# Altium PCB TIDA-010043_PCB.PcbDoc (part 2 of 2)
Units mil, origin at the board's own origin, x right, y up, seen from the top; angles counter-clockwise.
Board outline 2300 x 1555.91 mil, 4 copper layers (Top Layer, GND, PWR, Bottom Layer), stack 84.834 mil thick; 121 components, 65 nets, 295 pads, 120 vias.
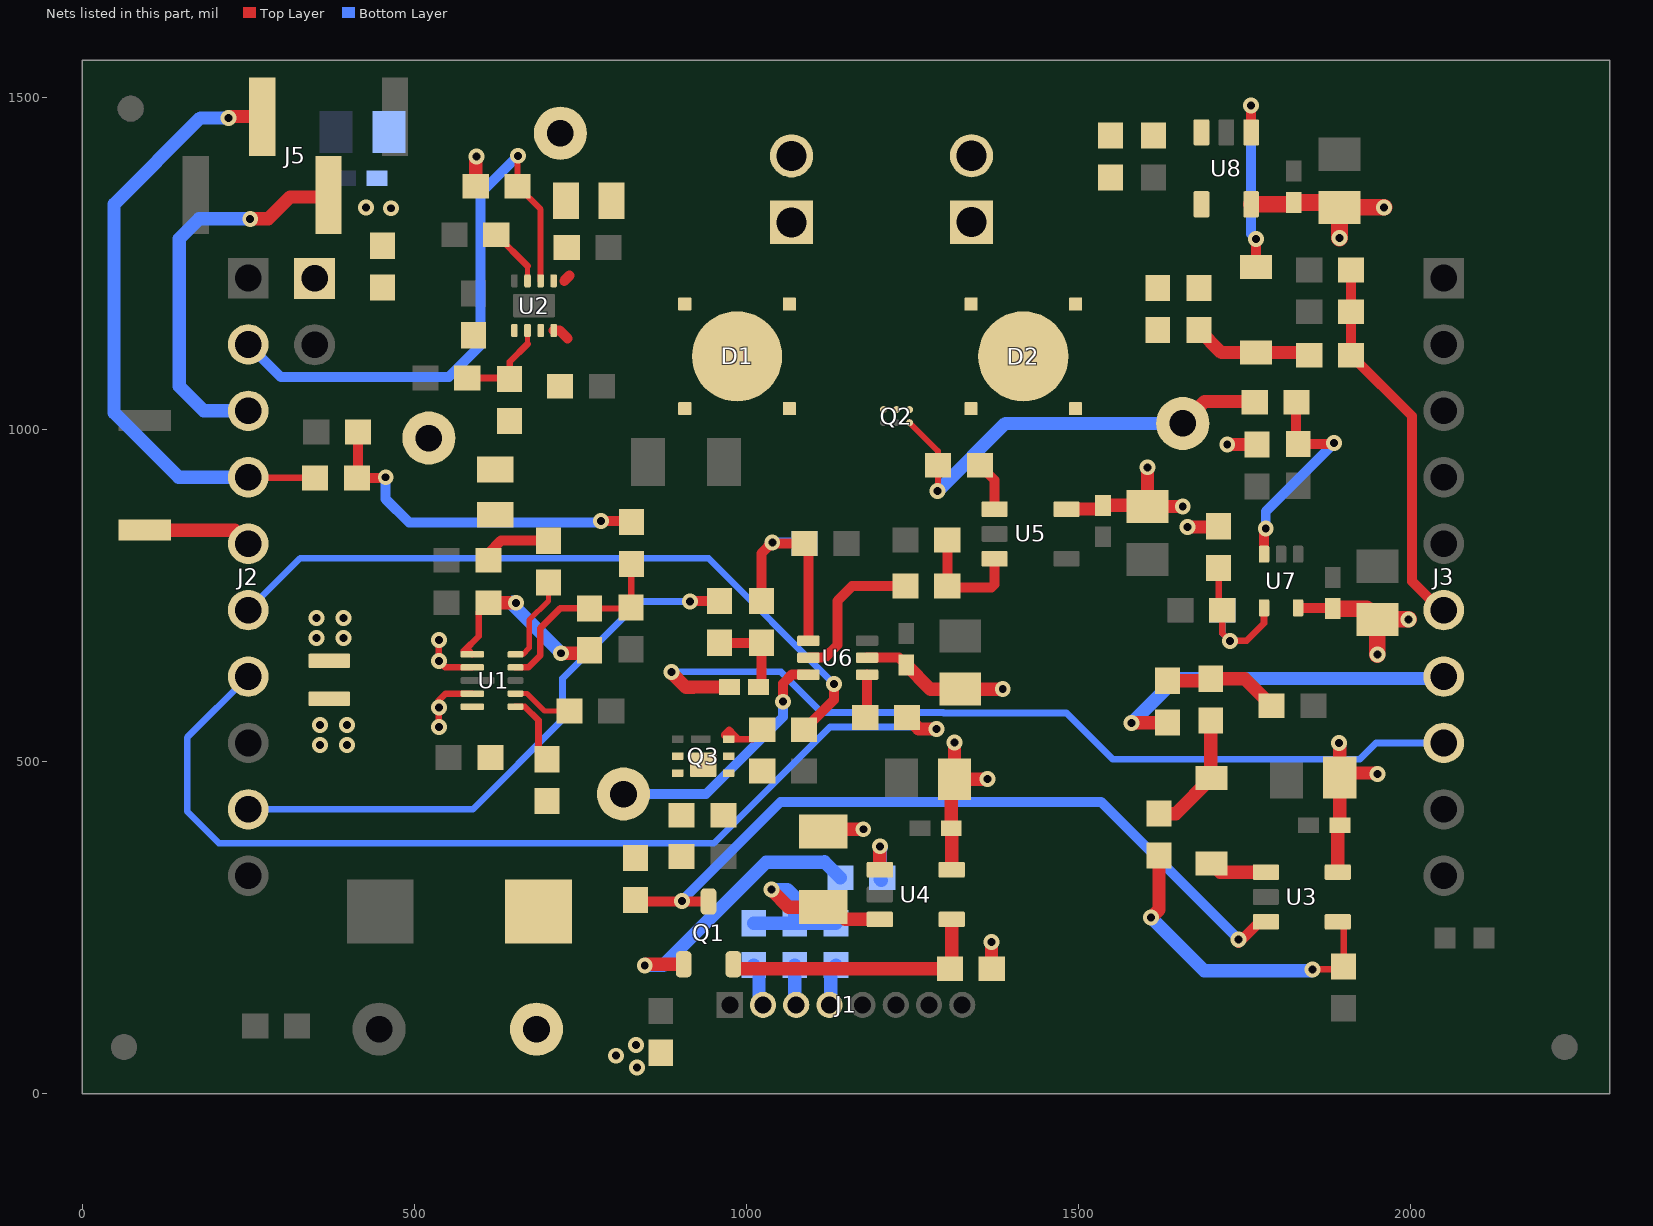
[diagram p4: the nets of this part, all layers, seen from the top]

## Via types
v1: diameter 24, hole 12, Top Layer to Bottom Layer, tented both sides, 114 vias
v2: diameter 24, hole 12, Top Layer to Bottom Layer, 4 vias
v3: diameter 19.68, hole 7.87, Top Layer to Bottom Layer, 2 vias

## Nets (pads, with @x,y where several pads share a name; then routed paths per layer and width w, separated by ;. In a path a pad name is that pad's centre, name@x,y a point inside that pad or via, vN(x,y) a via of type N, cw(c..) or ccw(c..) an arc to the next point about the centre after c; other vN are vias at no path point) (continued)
MUX_CTRL: J2.7 R30.1 | length 1513.6
  Top Layer w20: R30.1@1242.05,566.21 1259.26,549 v1(1286,549)
  Bottom Layer w10: J2.7@250,627.95 158,535.95 158,425 206,377 951,377 1125.87,551.87 1283.13,551.87 v1(1286,549)
NetC1_1: C1.1 C25.1 R5.1 U1.10 VIN.1
NetC2_1: C2.1 C3.1 R1.1 R4.2 R6.1 U1.6 | length 412
  Top Layer w9.84: U1.6@587.39,661.32 582.24,666.48 574.8,666.48 597,688.67 597,724.38 C3.1@611.62,739
  Top Layer w15: C2.1@611.62,803 611.62,813.82 630.24,832.44 R6.1@702,832.44
  Top Layer w20: C3.1@611.62,739 v1(653,739) ; v1(721,663) 759.5,663 R4.2@764,667.5
  Bottom Layer w20: v1(653,739) 649,739 648,740 646,738 v1(721,663)
NetC4_1: C4.1 R2.1 TP3.1 U2.5 | length 11.6
  Top Layer w15: 725.77,1223.77 734,1232
NetC5_1: C5.1 R1.2 R7.2 TP2.1 U2.3 U2.4 | length 26.1
  Top Layer w15: U2.4@709.85,1148.96 719.04,1148.96 731,1137
NetC6_1: C6.1 U2.1
NetC7_1: C7.1 R12.1 R13.1 | length 536.1
  Top Layer w15: C7.1@415.5,996 415.5,929 R13.1@413.5,927 456,927 v1(457,928) ; v1(781,862) 826.5,862 R12.1@828,860.5 ; R12.1@830,868.5 R12.1@831.5,869.99
  Bottom Layer w15: v1(457,928) 457,895 492.37,859.63 778.63,859.63 v1(781,862)
NetC17_1: C17.1 R23.2 U5.3 | length 182
  Top Layer w15: C17.1@1302.5,833.53 R23.2@1302.5,764 1304.5,762 1369,762 1373.71,766.71 U5.3@1373.71,805.22
NetC22_1: C22.1 Q3.3 R29.2 | length 102.7
  Top Layer w10: Q3.3@973.39,533.59 972.9,533.59 966.48,540.01 ; Q3.3@980.8,533.59 988.1,533.59 ; 980.8,541 974.43,547.36 973.83,547.36 966.48,540.01 ; R29.2@1023.85,547.7 1009.74,533.59 988.1,533.59 ; 966.48,540.01 981.68,540.01 988.1,533.59
NetC23_1: C23.1 R31.1 R33.2 U7.4 | length 252.9
  Top Layer w10: R31.1@1711,791.22 1711,733.21 C23.1@1716.5,727.71 1716.5,693.22 v1(1728,681.71) 1753,681.71 1779.41,708.12 U7.4@1779.41,731.36
  Bottom Layer w10: R33.2@1716.5,727.71 1716.5,693.22 v1(1728,681.71)
NetC24_1: C24.1 R34.1 R36.2 U6.4 | length 342.3
  Top Layer w15: R34.1@1022.56,741.7 1022.56,813.56 v1(1039,830) 1040.79,828.21 R36.2@1087.5,828.21 1093.26,822.45 U6.4@1093.26,681.85
  Bottom Layer w15: v1(1039,830) 1085.71,830 C24.1@1087.5,828.21
NetC26_1: C26.1 R39.2 R40.1 | length 174.5
  Top Layer w20: R40.1@1634.29,621.5 1696.29,621.5 R39.2@1699.29,624.5 1750.3,624.5 C26.1@1790.79,584
NetD1_1: D1.1 D1.4 D1.5 J8.1
NetD1_2: D1.2 D1.3 D2.1 D2.4 Q2.A1 Q2.B1 Q2.C1 R16.1
NetD2_2: D2.2 D2.3 D2.5 J6.1
NetD3_2: D3.2 R34.2 R35.1 | length 131.3
  Top Layer w15: R35.1@959.56,678.71 R34.2@1022.56,678.71 1022.56,616.56 D3.2@1018.21,612.21
NetD4_1: D4.1 R38.2 R39.1 | length 189
  Top Layer w20: R38.2@1621.29,421.5 1646.31,421.5 D4.1@1700.29,475.47 1699.29,476.47 R39.1@1699.29,561.5 R39.1@1700.1,562.32
NetD4_2: D4.2 U3.1 | length 87.3
  Top Layer w20: D4.2@1700.29,346.53 1713.42,333.4 U3.1@1782.15,333.4
NetD5_1: D5.1 R14.2 R17.1 | length 181.9
  Top Layer w20: R14.2@1681.32,1149.72 1715.29,1115.75 D5.1@1767.32,1115.75 1843.44,1115.75 R17.1@1847.5,1111.68
NetD5_2: D5.2 U8.1 | length 287.1
  Top Layer w15: U8.1@1760,1447.22 v1(1760,1488) ; D5.2@1767.32,1244.68 v1(1767.32,1286.68)
  Bottom Layer w15: v1(1760,1488) 1760,1294 v1(1767.32,1286.68)
NetJ6_2: J6.2 J8.2 R2.2 R18.1
NetL1_1: L1.1 U1.9 | length 94.6
  Top Layer w9.84: v2(537,552) v2(537,581) 537,592 547.27,602.27 U1.9@587.39,602.27
  other v1: 358,525 398.65,525 358,555 398.65,555
NetL1_2: L1.2 U1.7 | length 86
  Top Layer w9.84: v2(537,683) v2(537,651.46) 546.82,641.64 U1.7@587.39,641.64
  other v1: 353,686 393.65,686 353,716 393.65,716
NetQ1_1: Q1.1 R21.2 | length 429.9
  Top Layer w20: v1(847,193) v1@848,194 ; v1@849,194 v1@848,194 ; Q1.1@905.6,194.76 848.76,194.76 v1@848,194
  Bottom Layer w20: v1(847,193) 875,193 1030.13,348.13 1117.56,348.13 1117.56,349 R21.2@1141.5,325.05
NetQ1_2: Q1.2 R15.1 U4.4 | length 404.3
  Top Layer w20: Q1.2@980.4,194.76 987.16,188 R15.1@1306.5,188 1309.13,190.63 U4.4@1309.13,262.28
NetQ1_3: Q1.3 R42.2 U3.3 | length 1156.1
  Top Layer w15: R42.2@833,291.5 835.26,289.24 Q1.3@943,289.24 ; v1(1741.29,232) 1741.29,227 1772.89,258.6 U3.3@1782.15,258.6
  Bottom Layer w15: v1(903,290) 903,290.71 1051.29,439 1534.29,439 v1(1741.29,232)
NetQ2_A2: Q2.A2 R22.2 R43.1 TP6.1 | length 655.9
  Top Layer w9: Q2.A2@1245.68,1010.16 1288.5,967.34 R22.2@1288.5,946 1288.5,907.5 v1(1288,907)
  Top Layer w20: TP6.1@1657,1009 1690.08,1042.08 1758.88,1042.08 R43.1@1764.5,1047.71
  Bottom Layer w20: v1(1288,907) 1390,1009 TP6.1@1657,1009
NetQ3_1: Q3.1 Q3.2 Q3.5 Q3.6 Q3.8 R25.1
NetR4_1: R4.1 R10.1 R12.2 U1.4 | length 301.3
  Top Layer w9.38: R4.1@764,730.5 825.05,730.5 R10.1@826.5,731.94 826.5,797 R12.2@827,797.5
  Top Layer w9.84: U1.4@652.35,641.64 671.61,641.64 689.98,660 689.98,700.98 719.5,730.5 R4.1@764,730.5
NetR5_2: R5.2 U1.1 | length 107.1
  Top Layer w9.84: U1.1@652.35,582.58 666.42,582.58 687,562 687,516.5 R5.2@700,503.5
NetR6_2: R6.2 U1.5 | length 135.2
  Top Layer w8: U1.5@652.35,661.32 663.39,661.32 672.9,670.83 672.9,712.82 702,741.93 R6.2@702,769.45
NetR7_1: R7.1 R11.2 U2.2 | length 146.6
  Top Layer w8: 670.48,1128.52 U2.2@670.48,1148.96
  Top Layer w10: R11.2@579.82,1077.37 643.82,1077.37 643.82,1101.87 670.48,1128.52
NetR8_2: R8.2 U1.2 | length 92
  Top Layer w8: U1.2@652.35,602.27 669.73,602.27 696,576 R8.2@733.5,576
NetR9_2: R9.2 U2.7 | length 88.7
  Top Layer w8: U2.7@670.48,1223.77 670.48,1246.02
  Top Layer w10: R9.2@623.5,1293 670.48,1246.02
NetR14_1: R14.1 R16.2 U8.4
NetR18_2: R18.2 R20.2 U8.3
NetR19_1: R19.1 R46.2 R47.2 R48.2 U4.3 | length 384.9
  Top Layer w20: v1(1038,307) 1038,306 1063.4,280.6 R19.1@1116,280.6 1130.2,280.6 1148.51,262.28 U4.3@1200.87,262.28
  Bottom Layer w20: R46.2@1011,256.5 R47.2@1072.94,256.5 ; v1(1038,307) 1062,307 1072.94,296.06 R47.2@1072.94,256.5 ; R48.2@1134.87,256.5 R47.2@1072.94,256.5
NetR21_1: R21.1 U4.1 | length 90.3
  Top Layer w20: U4.1@1200.87,337.09 1200.87,371.8 v1(1201.43,372.37)
  Bottom Layer w20: R21.1@1203,320.99 1201.43,322.56 v1(1201.43,372.37) v1@1203.38,370.41
NetR22_1: R22.1 U5.1 | length 75.2
  Top Layer w15: R22.1@1351.5,946 1373.71,923.79 U5.1@1373.71,880.02
NetR23_1: R23.1 U6.5 | length 229.9
  Top Layer w15: U6.5@1093.26,656.26 1117.87,656.26 1137,675.39 1137,742 1159,764 R23.1@1239.5,764
NetR25_2: R25.2 R26.2 R42.1 TP5.1 U6.6 | length 382.2
  Top Layer w15: v1(1055,590) 1055,617.33 1068.33,630.67 U6.6@1093.26,630.67
  Bottom Layer w15: TP5.1@815,451 939,451 1055,567 v1(1055,590)
NetR30_2: R30.2 U6.1 | length 65.6
  Top Layer w15: R30.2@1179.06,566.21 1181.85,569 U6.1@1181.85,630.67
NetR37_2: R37.2 R38.1 U3.4 | length 482.5
  Top Layer w10: v1(1852.29,187) 1894.79,187 R37.2@1899.29,191.5 U3.4@1899.29,249.73
  Top Layer w20: v1(1609.29,265) 1621.29,277 R38.1@1621.29,358.5
  Bottom Layer w20: v1(1609.29,265) 1689.29,185 1850.29,185 v1(1852.29,187)
NetR43_2: R43.2 R44.1 U7.3 | length 336.7
  Top Layer w15: U7.3@1779.41,812.07 1779.41,848.12 v1(1782,850.71) ; R43.2@1827.5,1047.71 1827.5,981.71 R44.1@1831,978.21 1883.65,978.21 v1(1885,979.56)
  Bottom Layer w15: v1(1782,850.71) 1782,876.56 v1(1885,979.56)
PEAK-DETECT: J3.7 R40.2 | length 553.5
  Top Layer w20: v1(1580,558) 1580.5,558.5 R40.2@1634.29,558.5
  Bottom Layer w20: v1(1580,558) 1647,625 2047.05,625 J3.7@2050,627.95
PWM_CAL: J2.9 R35.2 | length 875.8
  Top Layer w15: v1(915,741) 915.7,741.7 R35.2@959.56,741.7
  Bottom Layer w10: J2.9@250,427.95 587.95,427.95 723.13,563.13 723.13,625.13 839,741 v1(915,741)
PWM_DCDC: J2.4 J5.2 R13.2 | length 934.8
  Top Layer w10: J2.4@250,927.95 250.95,927 R13.2@350.5,927
  Top Layer w20: v1(220,1469) 222.06,1471.06 J5.2@271,1471.06
  Bottom Layer w20: v1(220,1469) 178,1469 48,1339 48,1025 145.05,927.95 J2.4@250,927.95
RANGE_SEL: J2.6 R29.1 | length 1080.6
  Top Layer w15: R29.1@1086.84,547.7 1132,592.86 v1(1132,616.91)
  Bottom Layer w10: J2.6@250,727.95 328.05,806 942.91,806 v1(1132,616.91)
RXD: J2.3 J5.3 | length 593.7
  Top Layer w20: v1(253,1317) 280,1317 313,1350 J5.3@368.06,1350 ; J5.3@368.06,1367 J5.3@371,1369.94
  Bottom Layer w20: J2.3@250,1027.95 183.05,1027.95 146,1065 146,1287 176,1317 v1(253,1317)
SW_CAL: D3.1 J3.8 | length 1326
  Top Layer w20: v1(887,635) 887,634 909,612 920,612 920.21,612.21 D3.1@974.9,612.21
  Bottom Layer w10: v1(887,635) 1052.11,635 1113.23,573.87 1296.3,573.87 1297.18,573 1482,573 1551.87,503.13 1923.13,503.13 1947.95,527.95 J3.8@2050,527.95
SW_X: J2.5 S2.1 | length 164.4
  Top Layer w20: S2.1@94,848.32 229.63,848.32 J2.5@250,827.95
TX_3: J1.2 R46.1 | length 65.7
  Bottom Layer w20: R46.1@1011,193.5 1019,185.5 1019,139.61 J1.2@1025,133.61
TX_N: J1.4 R48.1 | length 64
  Bottom Layer w20: J1.4@1125,133.61 1127,135.61 1127,185.63 R48.1@1134.87,193.5
TX_P: J1.3 R47.1 | length 60.7
  Bottom Layer w20: R47.1@1072.94,193.5 1072.94,135.68 J1.3@1075,133.61
V_FAULT: J2.2 R3.1 U2.6 | length 901.2
  Top Layer w9: v1(656,1412) 655.5,1411.5 R3.1@655.5,1366 690.16,1331.33 U2.6@690.16,1223.77
  Bottom Layer w15: J2.2@250,1127.95 298.95,1079 552,1079 600,1127 600,1356 v1(656,1412)
V_LED: C12.1 J3.6 R17.2 R41.2 | length 574.7
  Top Layer w15: R41.2@1910.5,1240.22 C12.1@1910.5,1177.22 R17.2@1910.5,1111.68 2002,1020.18 2002,771.3 2047.67,725.63 J3.6@2050,727.95
VCC_5V: C8.1 C9.1 C10.1 C11.1 C13.1 C14.1 C15.1 C16.1 C18.1 C19.1 C20.1 C21.1 C27.1 C28.1 R3.2 R15.2 R19.2 R24.2 R27.2 R31.2 R32.2 U3.5 U4.5 U5.5 U6.2 U7.5 U8.5 | length 1683.3
  Top Layer w15: U6.2@1181.85,656.26 1229.89,656.26 C16.1@1240.56,645.59 ; U7.5@1830.59,731.36 1881.73,731.36 C21.1@1883,730.09
  Top Layer w20: R3.2@592.5,1366 592.5,1409.5 v1(594,1411) ; R19.2@1116,394.77 1119.23,398 v1(1176,398) ; C16.1@1240.56,645.59 1277.14,609 C15.1@1322,609 v1(1386,609) ; U4.5@1309.13,337.09 1309.13,398.66 C11.1@1308.43,399.37 1308.43,468.37 C10.1@1313.43,473.37 ; v1(1313.43,528.43) C10.1@1313.43,473.37 ; v1(1363.37,473.37) C10.1@1313.43,473.37 ; v1(1369,228) 1369,188.5 R15.2@1369.5,188 ; U5.5@1481.98,880.02 1531.4,880.02 C14.1@1537,885.62 1602.38,885.62 C13.1@1604,884 ; v1(1604,943) C13.1@1604,884 ; v1(1657,884) C13.1@1604,884 ; v1(1664,853) 1696.78,853 1704.5,860.71 R31.2@1711,854.21 ; v1(1724,977.21) R32.2@1769,977.21 ; U3.5@1890.42,333.4 1890.42,400.89 C28.1@1893.53,404 1893.53,475.76 C27.1@1893.29,476 ; v1(1892.29,528) 1893.29,527 C27.1@1893.29,476 ; v1(1950,481) 1948.31,482.69 1899.98,482.69 C27.1@1893.29,476
  Top Layer w25: U8.5@1760,1338.95 1821.35,1338.95 C9.1@1824,1341.59 1885.62,1341.59 C8.1@1893,1334.22 ; C21.1@1883,730.09 1933.91,730.09 C20.1@1950,714 ; v1(1893,1288) C8.1@1893,1334.22 ; v1(1950,661) C20.1@1950,714 ; v1(1960.22,1334.22) C8.1@1893,1334.22 ; v1(1997.11,714) C20.1@1950,714
  other v1: 835,39 804,57 834,73 465,1333 427,1334
VCC_5V_LP: J4.1 R24.1
pads on no net: FID1.1 FID2.1 FID3.1 FID4.1 FID5.1 FID6.1 J1.6 J1.7 J1.8 J2.8 J2.10 J3.3 J3.4 J3.5 Q3.0 U2.9@662.6,1186.37 U2.9@698.04,1186.37

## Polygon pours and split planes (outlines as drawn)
NetJ6_2 on Top Layer "vdd" (solid, remove dead copper, pour order 104): 969,1379 904,1314 779,1314 776,1317 776,1375 782,1381 869,1381 951,1463 1420,1463 1486,1397 1568,1397 1574,1391 1574,1356 1568,1350 1440.95,1350 1411.95,1379
VCC_5V on Top Layer "Top Layer-No Net" (solid, pour order 78): 431,1258.3 434.3,1255 470,1255 474,1259 474,1311 514,1351 514,1392 507,1399 414,1399 405,1390 405,1313.46 431,1287.46
GND on Top Layer "Top Layer-No Net" (solid, pour order 76): 158,162 168,172 271,172 284,159 284,66 276,58 174,58 158,74
VCC_5V_LP on Top Layer "Top Layer-No Net" (solid, pour order 72): 385,1259 402,1259 426,1235 469,1235 470.7,1233.3 470.7,1193.7 461,1184 314,1184 301,1197 301,1252 308,1259
NetR18_2 on Top Layer "TOP_LAYER_NETR18_2_P052" (solid, remove dead copper, pour order 52): 1687.51,1418.51 1529.21,1418.51 1523.46,1424.26 1523.46,1480.46 1530.46,1487.46 1701.02,1487.46 1703,1485.48 1703,1434
NetL1_2 on Top Layer "TOP_LAYER_NETL1_2_P004" (solid, remove dead copper, pour order 4): 422,638 424,640 424,738 419,743.38 337.38,743.38 332,738 332,641 335,638
NetL1_1 on Top Layer "TOP_LAYER_NETL1_1_P012" (solid, remove dead copper, pour order 12): 414.62,502.62 423,511 422,512 422,601 418,605 414,605.3 338.3,605.3 330,597 330,518 345.38,502.62
NetC1_1 on Top Layer "TOP_LAYER_NETC1_1_P016" (solid, remove dead copper, pour order 16): 666,520 666,468.54 673.54,461 725.17,461 741.08,444.92 764,422 764,40 753,29 614,29 593,50 593,541.54 569,565.54 569,586.21 570.59,587.8 593,587.8 606.54,587.8 666,528.34
GNDP on Top Layer "TOP_LAYER_GNDP_P018" (solid, remove dead copper, pour order 18): 621.84,617.33 571.6,617.33 567,612.73 567,531 572,526 572,45 553,26 305,26 304,27 304,864 322,882 549,882 567,864 567,657 567,630 570,627 621.84,627
GND on Top Layer "TOP_LAYER_GND_P022" (solid, remove dead copper, pour order 22): 846,612 846,688.33 807,688.37 807,647 800,640 685.26,640 672.26,627 641.38,627 640.38,626 640.38,617.8 641,617.1 672.9,617.1 685.46,604.54 749,604.54 838.54,604.54
NetC6_1 on Top Layer "TOP_LAYER_NETC6_1_P026" (solid, remove dead copper, pour order 26): 654.69,1159 656.32,1157.37 656.32,1132.37 644.32,1120.37 568.32,1120.37 568.32,1159
GND on Top Layer "TOP_LAYER_GND_P028" (solid, remove dead copper, pour order 28): 646.63,1244.37 656,1235 656,1194.12 658.38,1191.73 658.38,1185.38 653,1180 642.38,1180 637,1185.38 558.38,1185.38 548.32,1175.32 548.32,1055.37 495,1055.37 495,1295 520.27,1320.27 583.73,1320.27 586.85,1316.85 592,1311.7 592,1259 606.63,1244.37
NetC5_1 on Top Layer "TOP_LAYER_NETC5_1_P030" (solid, remove dead copper, pour order 30): 486.37,1035.37 478,1027 478,933 491,920 725,920 738.32,933.32 738.32,1148.96 730.28,1157 695.32,1157 685,1146.68 685,1061.05 659.32,1035.37
NetC4_1 on Top Layer "TOP_LAYER_NETC4_1_P032" (solid, remove dead copper, pour order 32): 703.89,1215 704.89,1214 750,1214 751,1215 751,1353.99 751,1394 773,1416 773,1484 763,1494 683,1494 670.76,1481.76 670.76,1420.24 703.89,1387.11 703.89,1346
NetD1_1 on Top Layer "TOP_LAYER_NETD1_1_P036" (solid, remove dead copper, pour order 36): 1118,1153 1104,1139 893,1139 873,1159 873,1222 898,1247 1004,1247 1013,1257 1013,1338.95 1021.05,1347 1104,1347 1118,1333
NetD2_2 on Top Layer "TOP_LAYER_NETD2_2_P038" (solid, remove dead copper, pour order 38): 1401,1247 1390,1258 1390,1338 1382,1346 1295,1346 1289,1340 1289,1154.5 1302.5,1141 1525,1141 1543,1159 1543,1236 1532,1247
NetD1_2 on Top Layer "TOP_LAYER_NETD1_2_P040" (solid, remove dead copper, pour order 40): 1644,1080 1578,1014 1578,958 1555,935 1425,935 1364,996 1332,996 1320,996 1292.36,1023.64 1117.64,1023.64 1095,1001 870,1001 861,1010 861,1068 868,1075 1546,1075 1568,1097 1568,1168 1573,1173 1640,1173 1644,1169
I_SENSE on Top Layer "TOP_LAYER_I_SENSE_P042" (solid, remove dead copper, pour order 42): 1233,1017 1233,916 1205,888 943,888 928,903 928,988 932,992 1102,992 1127,1017
NetQ2_A2 on Top Layer "TOP_LAYER_NETQ2_A2_P044" (solid, remove dead copper, pour order 44): 1238,1017 1238,920 1265,893 1308,893 1315,900 1315,993 1289,1019 1241,1019
NetR14_1 on Top Layer "TOP_LAYER_NETR14_1_P054" (solid, remove dead copper, pour order 54): 1673.48,1359.95 1668.48,1354.78 1668.48,1294.95 1651.48,1277.95 1597.48,1277.95 1588.26,1268.72 1588.26,1190.18 1595.48,1182.95 1695.48,1182.95 1707,1194.46 1707,1350 1697.05,1359.95
LED_DRV_SUP on Top Layer "TOP_LAYER_LED_DRV_SUP_P058" (solid, remove dead copper, pour order 58): 828,152.58 829.58,152.58 834.33,157 991.61,157 996,152.61 996,114 992,110 992,109 987,104 847.46,104 828,123.46
NetQ3_1 on Top Layer "TOP_LAYER_NETQ3_1_P060" (solid, remove dead copper, pour order 60): 884,515 884,472.39 889.72,466.66 929.34,466.66 936,460 936,403 944,395 986,395 986,517 983,520 888,520
NetC22_1 on Top Layer "TOP_LAYER_NETC22_1_P062" (solid, remove dead copper, pour order 62): 961.21,564.36 968.85,572 1042,572 1048,566 1048,467 1045,464 1004,464 1000,468 1000,513 988,525 969,525 961.21,532.79
NetR25_2 on Top Layer "TOP_LAYER_NETR25_2_P064" (solid, remove dead copper, pour order 64): 799,329 924.7,329 934,338.3 934,436.54 865.54,505 787,505 766,484 766,400 784,382 784,344
VCC_5V on Top Layer "Top Layer-No Net" (solid, pour order 102): 800,88 889,88 896,81 896,40 879,23 795,23 785,33 785,75 798,88
NetC2_1 on Top Layer "Bottom Layer-+5V" (solid, remove dead copper, pour order 106): 653,841.69 655,839.69 655,825 653,823 653,778 632,757 632,667.21 620.79,656 570,656 570,668.91 591,689.91 591,890 594,893 650,893 653,890
VCC_5V on Bottom Layer "Top Layer-No Net" (solid, pour order 82): 411,1321 411,1346 424,1359 424,1477 434,1487 500,1487 503,1484 503,1329 492,1318 414,1318
NetL1_2 on Bottom Layer "Top Layer-No Net" (solid, pour order 92): 589,729 590,728 590,640 586,636 545.22,636 334,636 331,639 331,723 337,729
NetL1_1 on Bottom Layer "Top Layer-No Net" (solid, pour order 94): 594,512 595,513 595,601 591,605 550.22,605 339,605 336,602 336,518 342,512
I_SENSE on Bottom Layer "BOTTOM_LAYER_I_SENSE_P100" (solid, remove dead copper, pour order 100): 1234,1018 1234,917 1206,889 944,889 929,904 929,989 933,993 1103,993 1128,1018
I_SENSE on PWR "PWR_I_SENSE_P096" (solid, remove dead copper, pour order 96): 1234,1018 1234,917 1206,889 944,889 929,904 929,989 933,993 1103,993 1128,1018
VCC_5V on PWR "Top Layer-No Net" (solid, pour order 98): 378,1470.14 440.86,1533 485,1534 2127,1534 2273,1388 2273,238 2168,133 1135,133 1135,1014 1121,1028 939.33,1028 867,954.22 867,33 852,18 615,18 424.73,208.27 424.73,1248.27 378,1295
GND on GND "Top Layer-No Net" (solid, pour order 90): 18,1432 18,1516 37,1535 2267,1535 2293,1509 2293,23 2286,16 34,16 18,32
GNDP on GND "Top Layer-No Net" (solid, pour order 88): 692,1093 744,1145 744,1298 759,1313 904,1313 924,1293 924,982 924,891 739,706 739,576.25 792,523.25 792,57 766,31 315,31 292,54 292,915 470,1093

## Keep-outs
Keep-Out Layer:
  the board outline again, w10
  text ".Layer_Name" at 577,-1080.54 h60

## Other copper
Top Layer:
  text ".Layer_Name" at 577,-1080.54 h60
GND:
  text "'.Layer_Name'" at 829,-1082 h60
PWR:
  text "'.Layer_Name'" at 785,-1086 h60
Bottom Layer:
  text ".Layer_Name" at 577,-1080.54 h60

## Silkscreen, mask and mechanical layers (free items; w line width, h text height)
Top Overlay:
  lines w6: 328,577 328,674 339,674 ; 531,620 557,620 ; 922,574 930,566 981,566 ; 1613,1080.25 1622.25,1071 1687.62,1071 1720,1038.62 1720,1016.19 1730.49,1005.7 1741.73,1005.7 ; 1957,1113 1966,1122 1966,1274 2001,1309 2019,1309
  text "TIDA-010043-E2" at 930,1487 h40
  text ".Layer_Name" at 577,-1080.54 h60
Bottom Overlay:
  text ".Layer_Name" at 577,-1080.54 h60
Top Paste:
  text ".Layer_Name" at 577,-1080.54 h60
Bottom Paste:
  text ".Layer_Name" at 577,-1080.54 h60
Top Solder:
  text ".Layer_Name" at 577,-1080.54 h60
  text ".Layer_Name" at 577,-1080.54 h60
Bottom Solder:
  text ".Layer_Name" at 577,-1080.54 h60
Drill Guide:
  text ".Layer_Name" at 577,-1080.54 h60
M1 Board Outline:
  the board outline again, w10
M2 Board Dimensions:
  rectangle: 0,-497.05 125,-372.05
  rectangle: 125,-622.05 500,-497.05
  lines w7: 0,-497.05 1000,-497.05 ; 125,-622.05 125,-372.05 ; 250,-622.05 250,-372.05 ; 500,-622.05 500,-372.05 ; 750,-622.05 750,-372.05 ; 0,-622.05 1000,-622.05 1000,-372.05 0,-372.05 0,-622.05
M3 3D STEP Top:
  text ".Layer_Name" at 577,-1080.54 h60
M4 3D STEP Bottom:
  text ".Layer_Name" at 577,-1080.54 h60
M5 Assembly Top:
  lines w10: -292,-1152.21 6308,-1152.21 ; -292,-948.88 6310,-948.88 ; -292,-745.55 -292,-1355.55 3713,-1355.55 6310,-1355.55 6310,-745.55 -291.5,-745.55 -291.5,-1355.55 1284,-1355.55 ; 2173,-1355.55 2173,-745.55 ; 3440,-948.88 3440,-745.55 ; 4280,-948.88 4280,-745.55 ; 4902,-1362.05 4902,-1159.21
  text "COMPONENTS MARKED 'DNP' SHOULD NOT BE POPULATED." at 1153.5,-540.55 h30
  text "ASSEMBLY VARIANT:" at 1153,-656.05 h30
  text ".VariantName" at 2189,-656.05 h30
  text "PCB VIEWED FROM TOP SIDE" at -228.5,-877.71 h30
  text "BOARD #:" at 2248,-877.71 h30
  text ".PRJ_Number" at 2793.5,-877.71 h30
  text "REV:" at 3638,-877.71 h30
  text ".PCB_Rev" at 3929.5,-877.71 h30
  text "SVN REV:" at 4476,-877.71 h30
  text ".VersionControl_RevNumber" at 4982,-877.71 h30
  text "TID #:" at 2248,-1081.05 h30
  text ".TID" at 2793.5,-1081.05 h30
  text "'.Layer_Name'" at 698,-1086 h30
  text "PLOT NAME =" at -228.5,-1286.38 h30
  text ".plot_File_Name" at 577,-1286.38 h30
  text "GENERATED    :" at 2250,-1286.38 h30
  text ".Print_Date" at 3119.5,-1286.38 h30
  text ".Print_Time" at 3848.5,-1286.38 h30
  text "TEXAS INSTRUMENTS" at 5113,-1286.38 h30
M6 Assembly Bottom:
  circle w6: c352,1228.95 r12.01
  circle w6: c244,1230.95 r12.01
  circle w6: c2050,1227.95 r12.01
  lines w10: -292.5,-949.38 6309.5,-949.38 ; -290.5,-1152.71 6309.5,-1152.71 ; 1115.5,-1362.55 1115.5,-1159.71 ; 1737.5,-949.38 1737.5,-746.05 ; 2577.5,-949.38 2577.5,-746.05 ; 3844.5,-1356.05 3844.5,-746.05 ; 4733.5,-1356.05 6309,-1356.05 6309,-746.05 -292.5,-746.05 -292.5,-1356.05 2304.5,-1356.05 6309.5,-1356.05 6309.5,-746.05
  text "COMPONENTS MARKED 'DNP' SHOULD NOT BE POPULATED." at 6102,-540.05 h30
  text ".VariantName" at 5058,-656.05 h30
  text "ASSEMBLY VARIANT:" at 6097,-656.05 h30
  text ".VersionControl_RevNumber" at 1035.5,-878.21 h30
  text "SVN REV:" at 1541.5,-878.21 h30
  text ".PCB_Rev" at 2088,-878.21 h30
  text "REV:" at 2379.5,-878.21 h30
  text ".PRJ_Number" at 3224,-878.21 h30
  text "BOARD #:" at 3769.5,-878.21 h30
  text "PCB VIEWED FROM BOTTOM SIDE" at 6246,-878.21 h30
  text ".TID" at 3224,-1081.55 h30
  text "TID #:" at 3769.5,-1081.55 h30
  text "'.Layer_Name'" at 5209,-1088 h30
  text "TEXAS INSTRUMENTS" at 904.5,-1286.88 h30
  text ".Print_Time" at 2169,-1286.88 h30
  text ".Print_Date" at 2898,-1286.88 h30
  text "GENERATED    :" at 3767.5,-1286.88 h30
  text ".plot_File_Name" at 5440.5,-1286.88 h30
  text "PLOT NAME =" at 6246,-1286.88 h30
M9 Title Sheet:
  drawing of 57 lines, arcs and shapes, not listed
  text "1" at 739.84,7814.45 h70
  text "2" at 3235.5,7814.45 h70
  text "3" at 5724.84,7814.45 h70
  text "4" at 8231.51,7814.45 h70
  text "5" at 10730.5,7814.45 h70
  text "6" at 13235.5,7814.45 h70
  text "A" at -416.5,6671.45 h70
  text "A" at 14383.5,6671.45 h70
  text "B" at -416.5,4291.45 h70
  text "B" at 14383.5,4291.45 h70
  text "C" at -416.5,1916.45 h70
  text "C" at 14383.5,1916.45 h70
  text "PROJECT TITLE:" at 11343.5,55.45 h45
  text ".PRJ_Title" at 11393.5,-77.87 h70
  text "DESIGNED FOR:" at 11343.5,-245.55 h45
  text ".PRJ_Customer" at 11393.5,-385.55 h70
  text "D" at -416.5,-453.55 h70
  text "D" at 14383.5,-453.55 h70
  text "FILE NAME:" at 11343.5,-545.55 h45
  text ".PCB_File_Name_No_Path" at 11393.5,-665.55 h70
  text "Texas Instruments (TI) and/or its licensors do not warrant the accuracy or completeness of this specification" at 6374,-827.39 h45
  text "ENGINEER:" at 11343.5,-835.55 h45
  text "LAYOUT BY:" at 12848.5,-835.55 h45
  text "or any information contained therein. TI and/or its licensors do not warrant that this design will meet" at 6329.01,-940.05 h45
  text ".PRJ_Engineer" at 11393.5,-990.54 h70
  text ".PCB_Layout" at 12899,-990.54 h70
  text "the specifications, will be suitable for your application or fit for any particular purpose, or will operate in" at 6329.01,-1052.72 h45
  text "ALTIUM DESIGNER VERSION:" at 12848.5,-1145.55 h45
  text "an implementation. TI and/or its licensors do not warrant that the design is production worthy. You should" at 6329.01,-1165.38 h45
  text "completely validate and test your design implementation to confirm the system functionality for your application." at 6374,-1278.05 h45
  text ".print_Scale" at 11393.5,-1278.87 h70
  text ".Application_BuildNumber" at 12899,-1278.87 h70
  text "1" at 739.84,-1485.55 h70
  text "2" at 3235.5,-1485.55 h70
  text "3" at 5724.84,-1485.55 h70
  text "4" at 8231.51,-1485.55 h70
  text "5" at 10730.5,-1485.55 h70
  text "6" at 13235.5,-1485.55 h70
M10 Fab Notes:
  drawing of 173 lines, arcs and shapes, not listed
  text "DESIGN INFORMATION" at 12378.02,5978.95 h60
  text "MIN. TRACK WIDTH:" at 11733.46,5798.95 h60
  text "8" at 12829.7,5798.96 h60
  text "MIL" at 12984.46,5798.95 h60
  text "MIN. CLEARANCE:" at 11733.46,5666.95 h60
  text "6" at 12769.7,5666.96 h60
  text "MIL" at 12984.46,5666.95 h60
  text "19.68" at 12721,5540 h60
  text "MIL" at 13018,5539 h60
  text "MIN. VIA PAD SIZE:" at 11733.46,5534.95 h60
  text "0.05mm (2MIL)" at 12428.46,5393.24 h60
  text "MINIMUM ANNULAR RING" at 11404.23,5388.96 h60
  text "EXTERNAL" at 13136.46,5388.96 h60
  text "PER" at 11604.23,5270.96 h60
  text "IPC-D-275 CLASS 2 LEVEL C" at 11824.23,5270.95 h60
  text "MIL, HOLES" at 13312.46,5158.67 h60
  text "+/-" at 12920,5157.95 h60
  text "+/-" at 13774,5157.95 h60
  text "REGISTRATION TOLERANCES:" at 11404.23,5152.95 h60
  text "METAL" at 12604,5152.95 h60
  text "5" at 13180.2,5152.96 h60
  text "3" at 14013.2,5152.96 h60
  text "MIL" at 14129.46,5152.95 h60
  text "+/-" at 13774,5039.95 h60
  text "HOLE SIZE TOLERANCE (UNLESS OTHERWISE SPECIFIED):" at 11404.23,5034.95 h60
  text "3" at 14013.2,5034.96 h60
  text "MIL" at 14129.46,5034.95 h60
  text "MATERIAL:" at 11329.46,4825.5 h60
  text "FR-4 High Tg" at 12315.9,4685.16 h60
  text "FR-408" at 11750.46,4676.59 h60
  text "OTHER" at 13238.46,4676.59 h60
  text "X" at 12161,4672.95 h60
  text "62 MIL (1.6mm) +/-10%" at 12070.56,4513.88 h60
  text "THICKNESS:" at 11404.23,4509.59 h60
  text "X" at 11942.4,4509.59 h60
  text "OTHER" at 13355.46,4509.59 h60
  text "TOLERANCE:" at 11404.23,4351.59 h60
  text "X" at 12243.53,4351.59 h60
  text "ANSI IPC-6012 TYPE 3 CLASS 2" at 12430.48,4351.59 h60
  text "OTHER +/-" at 12430.46,4195.59 h60
  text "BOW & TWIST:" at 11404.23,4038.59 h60
  text "X" at 12243.53,4038.59 h60
  text "ANSI IPC-6012 TYPE 3 CLASS 2" at 12430.48,4038.59 h60
  text "OTHER +/-" at 12430.46,3880.08 h60
  text "DRILLING:" at 11329.46,3741.59 h60
  text "REFERENCE:" at 11404.23,3624.59 h60
  text "X" at 12052.46,3624.59 h60
  text "AS SHOWN" at 12239.46,3624.59 h60
  text "X" at 12953.46,3624.59 h60
  text "NC_DRILL FILES" at 13090.46,3624.59 h60
  text "PTH COPPER THICKNESS:" at 11404.23,3466.59 h60
  text "X" at 12534.46,3466.59 h60
  text "20-30 um" at 12671.46,3466.59 h60
  text "OTHER" at 13388.46,3466.59 h60
  text "BOARD FINISH:" at 11329.46,3307.59 h60
  text "SILKSCREEN:" at 11484.68,3189.59 h60
  text "X" at 12433.46,3189.59 h60
  text "TOP" at 12559.46,3189.59 h60
  text "X" at 12943.46,3189.59 h60
  text "BOTTOM" at 13070.46,3189.59 h60
  text "SILKSCREEN COLOR:" at 11484.68,3022.59 h60
  text "X" at 12432.42,3022.59 h60
  text "WHITE" at 12559.46,3022.59 h60
  text "OTHER" at 13070.46,3022.59 h60
  text "X" at 12563.42,2863.4 h60
  text "GREEN" at 12690.46,2863.4 h60
  text "OTHER" at 13308.46,2863.4 h60
  text "SOLDER RESIST COLOR:" at 11484.68,2852.59 h60
  text "X" at 12563.42,2693.4 h60
  text "MATTE" at 12690.46,2693.4 h60
  text "SEMI-GLOSS" at 13308,2692.76 h60
  text "IMMERSION GOLD (ENIG)" at 12390.46,2504.88 h60
  text "ENEPIG" at 13728,2501.59 h60
  text "SURFACE FINISH:" at 11329.46,2500.59 h60
  text "X" at 12203.51,2500.59 h60
  text "IMM. TIN/SILVER OR EQUIV" at 11659,2343.59 h60
  text "OTHER" at 13090.46,2343.59 h60
  text "ARRAY/PANEL:" at 11329.46,2164.59 h60
  text "CUT AND TRIM PER M1 BOARD OUTLINE" at 12390.46,2160.31 h60
  text "N.C. ROUTE" at 12390.46,2008.59 h60
  text "X" at 13069.46,2008.59 h60
  text "V. SCORE" at 13256.46,2008.59 h60
  text "CERTIFICATION:" at 11329.46,1871.59 h60
  text "MATERIALS AND WORKMANSHIP FOR ALL PCBS" at 12054.46,1871.59 h60
  text "TO MEET OR EXCEED THE REQUIREMENTS OF:" at 12054.46,1773.59 h60
  text "X" at 11680.96,1637.09 h60
  text "ANSI IPC-A-600F CLASS ->" at 11819.96,1637.09 h60
  text "X" at 13459.02,1637.09 h60
  text "2" at 13577.96,1637.09 h60
  text "1" at 13262.96,1635.59 h60
  text "3" at 13931.96,1635.59 h60
  text "X" at 12495.02,1477.59 h60
  text "RoHS" at 12631.96,1477.59 h60
  text "OTHER" at 13276.36,1477.59 h60
  text "PER ORDER" at 13673.42,1477.59 h60
  text "ALL BOARDS MUST MEET OR EXCEED UL94-V0 REQUIREMENTS." at 11357,1311.95 h60
  text "PCB MUST BEAR THE UL94V-0 UL REGISTERED MATERIAL ID NUMBER" at 11357,1191.95 h60
  text "ADDITIONAL REQUIREMENTS:" at 11329.46,1018.59 h60
  text "MICROSECTION:" at 11404.23,903.59 h60
  text "YES" at 12309.96,903.59 h60
  text "REQUIRED" at 13171.46,747.45 h60
  text "BARE BOARD ELEC. TEST:" at 11404.23,744.59 h60
  text "NONE" at 12709.96,744.59 h60
  text "X" at 13044.46,744.59 h60
  text "PER ORDER" at 13763.46,744.59 h60
M11 Gerber Information:
  lines w10: -292,-1152.21 6308,-1152.21 ; -292,-948.88 6310,-948.88 ; -292,-745.55 -292,-1355.55 3713,-1355.55 6310,-1355.55 6310,-745.55 -291.5,-745.55 -291.5,-1355.55 1284,-1355.55 ; 2173,-1355.55 2173,-745.55 ; 3440,-948.88 3440,-745.55 ; 4280,-948.88 4280,-745.55 ; 4902,-1362.05 4902,-1159.21
  text "ALL ARTWORK VIEWED FROM TOP SIDE" at -228.5,-877.71 h60
  text "BOARD #:" at 2248,-877.71 h60
  text ".PRJ_Number" at 2793.5,-877.71 h60
  text "REV:" at 3638,-877.71 h60
  text ".PCB_Rev" at 3929.5,-877.71 h60
  text "SVN REV:" at 4476,-877.71 h60
  text ".VersionControl_RevNumber" at 4982,-877.71 h60
  text "LAYER NAME =" at -228.5,-1080.54 h60
  text "TID #:" at 2248,-1081.05 h60
  text ".TID" at 2793.5,-1081.05 h60
  text "PLOT NAME =" at -228.5,-1286.38 h60
  text ".plot_File_Name" at 577,-1286.38 h60
  text "GENERATED    :" at 2250,-1286.38 h60
  text ".Print_Date" at 3119.5,-1286.38 h60
  text ".Print_Time" at 3848.5,-1286.38 h60
  text "TEXAS INSTRUMENTS" at 5113,-1286.38 h60
M12 Stackup:
  drawing of 295 lines, arcs and shapes, not listed
  text "Layer" at 9797.84,7585.45 h60
  text "Name" at 10207.76,7585.45 h60
  text "Material" at 11137.5,7585.45 h60
  text "Thickness" at 11997.27,7585.45 h60
  text "Constant" at 12647.1,7585.45 h60
  text "Board Layer Stack" at 13216.96,7585.45 h60
  text "1" at 9797.84,7465.45 h60
  text "Top Overlay" at 10207.76,7465.45 h60
  text "2" at 9797.84,7345.45 h60
  text "Top Solder" at 10207.76,7345.45 h60
  text "Solder Resist" at 11137.5,7345.45 h60
  text "0.40mil" at 11997.27,7345.45 h60
  text "3.5" at 12647.1,7345.45 h60
  text "3" at 9797.84,7225.45 h60
  text "Top Layer" at 10207.76,7225.45 h60
  text "Copper" at 11137.5,7225.45 h60
  text "1.40mil" at 11997.27,7225.45 h60
  text "4" at 9797.84,7105.45 h60
  text "Dielectric 2" at 10207.76,7105.45 h60
  text "FR-4 High Tg" at 11137.5,7105.45 h60
  text "10.00mil" at 11997.27,7105.45 h60
  text "4.2" at 12647.1,7105.45 h60
  text "5" at 9797.84,6985.45 h60
  text "GND" at 10207.76,6985.45 h60
  text "Copper" at 11137.5,6985.45 h60
  text "1.42mil" at 11997.27,6985.45 h60
  text "6" at 9797.84,6865.45 h60
  text "Dielectric1" at 10207.76,6865.45 h60
  text "FR-4 High Tg" at 11137.5,6865.45 h60
  text "59.20mil" at 11997.27,6865.45 h60
  text "4.8" at 12647.1,6865.45 h60
  text "7" at 9797.84,6745.45 h60
  text "PWR" at 10207.76,6745.45 h60
  text "Copper" at 11137.5,6745.45 h60
  text "1.42mil" at 11997.27,6745.45 h60
  text "8" at 9797.84,6625.45 h60
  text "Dielectric 3" at 10207.76,6625.45 h60
  text "FR-4 High Tg" at 11137.5,6625.45 h60
  text "10.00mil" at 11997.27,6625.45 h60
  text "4.2" at 12647.1,6625.45 h60
  text "9" at 9797.84,6505.45 h60
  text "Bottom Layer" at 10207.76,6505.45 h60
  text "Copper" at 11137.5,6505.45 h60
  text "1.40mil" at 11997.27,6505.45 h60
  text "10" at 9797.84,6385.45 h60
  text "Bottom Solder" at 10207.76,6385.45 h60
  text "Solder Resist" at 11137.5,6385.45 h60
  text "0.40mil" at 11997.27,6385.45 h60
  text "3.5" at 12647.1,6385.45 h60
  text "11" at 9797.84,6265.45 h60
  text "Bottom Overlay" at 10207.76,6265.45 h60
M13 Component Bodies Top:
  text ".Layer_Name" at 577,-1080.54 h60
M14 Component Bodies Bottom:
  text ".Layer_Name" at 577,-1080.54 h60
M15 Courtyards Top:
  text ".Layer_Name" at 577,-1080.54 h60
M16 Courtyards Bottom:
  text ".Layer_Name" at 577,-1080.54 h60
Drill Drawing:
  circle w10: c5457.4,3146.66 r27.66
  lines w10: 5429.75,2634.99 5443.58,2634.99 5443.58,2621.16 5471.23,2621.16 5471.23,2634.99 5485.06,2634.99 5485.06,2662.65 5471.23,2662.65 5471.23,2676.48 5443.58,2676.48 5443.58,2662.65 5429.75,2662.65 5429.75,2634.99 ; 5429.75,2773.28 5457.4,2745.62 5485.06,2773.28 5457.4,2800.94 5429.75,2773.28 ; 5429.75,2870.08 5485.06,2870.08 5485.06,2925.4 5429.75,2925.4 5429.75,2870.08 ; 5429.75,3008.37 5443.58,3008.37 5457.4,2994.54 5471.23,3008.37 5485.06,3008.37 5471.23,3022.2 5485.06,3036.03 5471.23,3036.03 5457.4,3049.86 5443.58,3036.03 5429.75,3036.03 5443.58,3022.2 5429.75,3008.37 ; 5429.75,3243.46 5457.4,3257.29 5485.06,3243.46 5471.23,3271.12 5485.06,3298.77 5457.4,3284.94 5429.75,3298.77 5443.58,3271.12 5429.75,3243.46
  lines w12: 5379.6,2583.83 8612.37,2583.83 ; 5379.6,3330.58 8612.37,3330.58 ; 5717.77,2459.37 5717.77,3455.04 ; 6049.89,2459.37 6049.89,3455.04 ; 6686.89,2459.37 6686.89,3455.04 ; 6946.24,2459.37 6946.24,3455.04 ; 7321.66,2459.37 7321.66,3455.04 ; 8045.51,2459.37 8045.51,3455.04 ; 5379.6,2459.37 8612.37,2459.37 8612.37,3455.04 5379.6,3455.04 5379.6,2459.37
  text "Symbol" at 5454.28,3367.92 h72
  text "Quantity" at 5755.11,3367.92 h72
  text "Finished Hole Size" at 6087.22,3367.92 h72
  text "Plated" at 6724.23,3367.92 h72
  text "Hole Type" at 6983.58,3367.92 h72
  text "Drill Layer Pair" at 7359,3367.92 h72
  text "Hole Tolerance" at 8082.85,3367.92 h72
  text "2" at 5755.11,3243.46 h60
  text "7.87mil (0.200mm)" at 6087.22,3243.46 h60
  text "PTH" at 6724.23,3243.46 h60
  text "Round" at 6983.58,3243.46 h60
  text "Top Layer - Bottom Layer" at 7359,3243.46 h60
  text "118" at 5755.11,3119 h60
  text "12.00mil (0.305mm)" at 6087.22,3119 h60
  text "PTH" at 6724.23,3119 h60
  text "Round" at 6983.58,3119 h60
  text "Top Layer - Bottom Layer" at 7359,3119 h60
  text "8" at 5755.11,2994.54 h60
  text "25.59mil (0.650mm)" at 6087.22,2994.54 h60
  text "PTH" at 6724.23,2994.54 h60
  text "Round" at 6983.58,2994.54 h60
  text "Top Layer - Bottom Layer" at 7359,2994.54 h60
  text "7" at 5755.11,2870.08 h60
  text "40.00mil (1.016mm)" at 6087.22,2870.08 h60
  text "PTH" at 6724.23,2870.08 h60
  text "Round" at 6983.58,2870.08 h60
  text "Top Layer - Bottom Layer" at 7359,2870.08 h60
  text "21" at 5755.11,2745.62 h60
  text "40.16mil (1.020mm)" at 6087.22,2745.62 h60
  text "PTH" at 6724.23,2745.62 h60
  text "Round" at 6983.58,2745.62 h60
  text "Top Layer - Bottom Layer" at 7359,2745.62 h60
  text "4" at 5755.11,2621.16 h60
  text "45.28mil (1.150mm)" at 6087.22,2621.16 h60
  text "PTH" at 6724.23,2621.16 h60
  text "Round" at 6983.58,2621.16 h60
  text "Top Layer - Bottom Layer" at 7359,2621.16 h60
  text "160 Total" at 5755.11,2496.71 h60
  text "Drill Tolarence:" at 5392,2108 h60
  text "FOR 7.87MIL DRILL +0/-7.87MIL" at 5396,1994.79 h60
  text "FOR 12MIL DRILL +0/-12MIL" at 5391.23,1898.09 h60
  text "FOR PTH DRILL +/-3MIL" at 5393,1816.79 h60
  text "FOR NPTH DRILL +/-2MIL" at 5392,1723.79 h60
  text "THIS IS NOT AN IMPEDENCE CONTROLLED BOARD" at 5362,1620.79 h60
  text "ALL VIAS ARE TENTED VIAS EXCEPT THEMAL VIAS" at 5373,1526 h60
  text ".Layer_Name" at 577,-1080.54 h60
M17 Embedded Cavity:
  text ".Layer_Name" at 577,-1080.54 h60
M18 Embedded Assembly:
  text ".Layer_Name" at 577,-1080.54 h60
M19 Embedded Keepout:
  text ".Layer_Name" at 577,-1080.54 h60

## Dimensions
0,0 to 2300,0 on M2 Board Dimensions
0,-622.05 to 1000,-622.05 on M2 Board Dimensions
0,0 to 0,1555.91 on M2 Board Dimensions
